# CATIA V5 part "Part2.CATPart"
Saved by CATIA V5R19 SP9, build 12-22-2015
Part number: Part2
Bounding box of the stored display mesh (mm): x -172.5 to 172.5, y -250 to 250, z 0 to 10
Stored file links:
  Z:\charly_robot\plaque a trous\Part2.CATPart
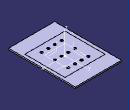
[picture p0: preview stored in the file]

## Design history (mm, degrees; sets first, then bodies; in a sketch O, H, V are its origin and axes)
AxisSystem1: origin (0, 0, 0), X (1, 0, 0), Y (0, 1, 0), Z (0, 0, 1)
Body1 (main body)
  Sketch1 on XY plane of AxisSystem1, origin (0, 0, 0), H (1, 0, 0), V (0, 1, 0)
    line L1 (172.5, 250) -> (172.5, -250)
    line L2 (172.5, -250) -> (-172.5, -250)
    line L3 (-172.5, -250) -> (-172.5, 250)
    line L4 (-172.5, 250) -> (172.5, 250)
    length L4 = 345
    length L1 = 500
    vertical: L1 V, L3 V
    horizontal: L2 H, L4 H
    equidistance: L1 L3 O, L2 L4 O
  Pad1: profile Sketch1, direction (0, 0, 1), length 10
  Plane1: type Offset, RefPlane XY plane of AxisSystem1, Offset 4
  Sketch2 on Plane1, origin (4.3198, -8.9368, 4), H (1, 0, 0), V (0, 1, 0)
    point P1 (-79.3198, -91.0632)
    reference projected line E1 through (-4.3198, 0) direction (0, 1) from edge [YZ plane of AxisSystem1 | XY plane of AxisSystem1]
    reference projected line E2 through (0, 8.9368) direction (1, 0) from edge [XY plane of AxisSystem1 | ZX plane of AxisSystem1]
    distance P1 E1 = 75
    distance E2 P1 = 100
  Hole1: placed by Sketch2, at (-75, -100, 4) direction (0, 0, -1), diameter 6.5, through (limit type 6), counterbore diameter 20, counterbore depth 4
  RectPattern1: of Hole1, direction 1 instances 4, spacing 50, along X axis, direction 2 instances 3, spacing 100, along Y axis
  Sketch3 on end face of Pad1, origin (0, 0, 10), H (1, 0, 0), V (0, 1, 0)
    line L1 (150, 150) -> (150, -150)
    line L2 (150, -150) -> (-150, -150)
    line L3 (-150, -150) -> (-150, 150)
    line L4 (-150, 150) -> (150, 150)
    length L1 = 300
    length L4 = 300
    vertical: L1 V, L3 V
    horizontal: L2 H, L4 H
    equidistance: L1 L3 O, L2 L4 O
  Pocket1: profile Sketch3, direction (0, 0, -1), length 0.1, thin wall 0.1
